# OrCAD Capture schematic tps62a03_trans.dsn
size D; title: TPS62A03x 3A, High-Efficiency, Synchronous, Buck Converter; rev: 1.0; note: Datasheet: SLUSFD4A     EVM: SLUUD12; note: Synchronous Step Down Converter
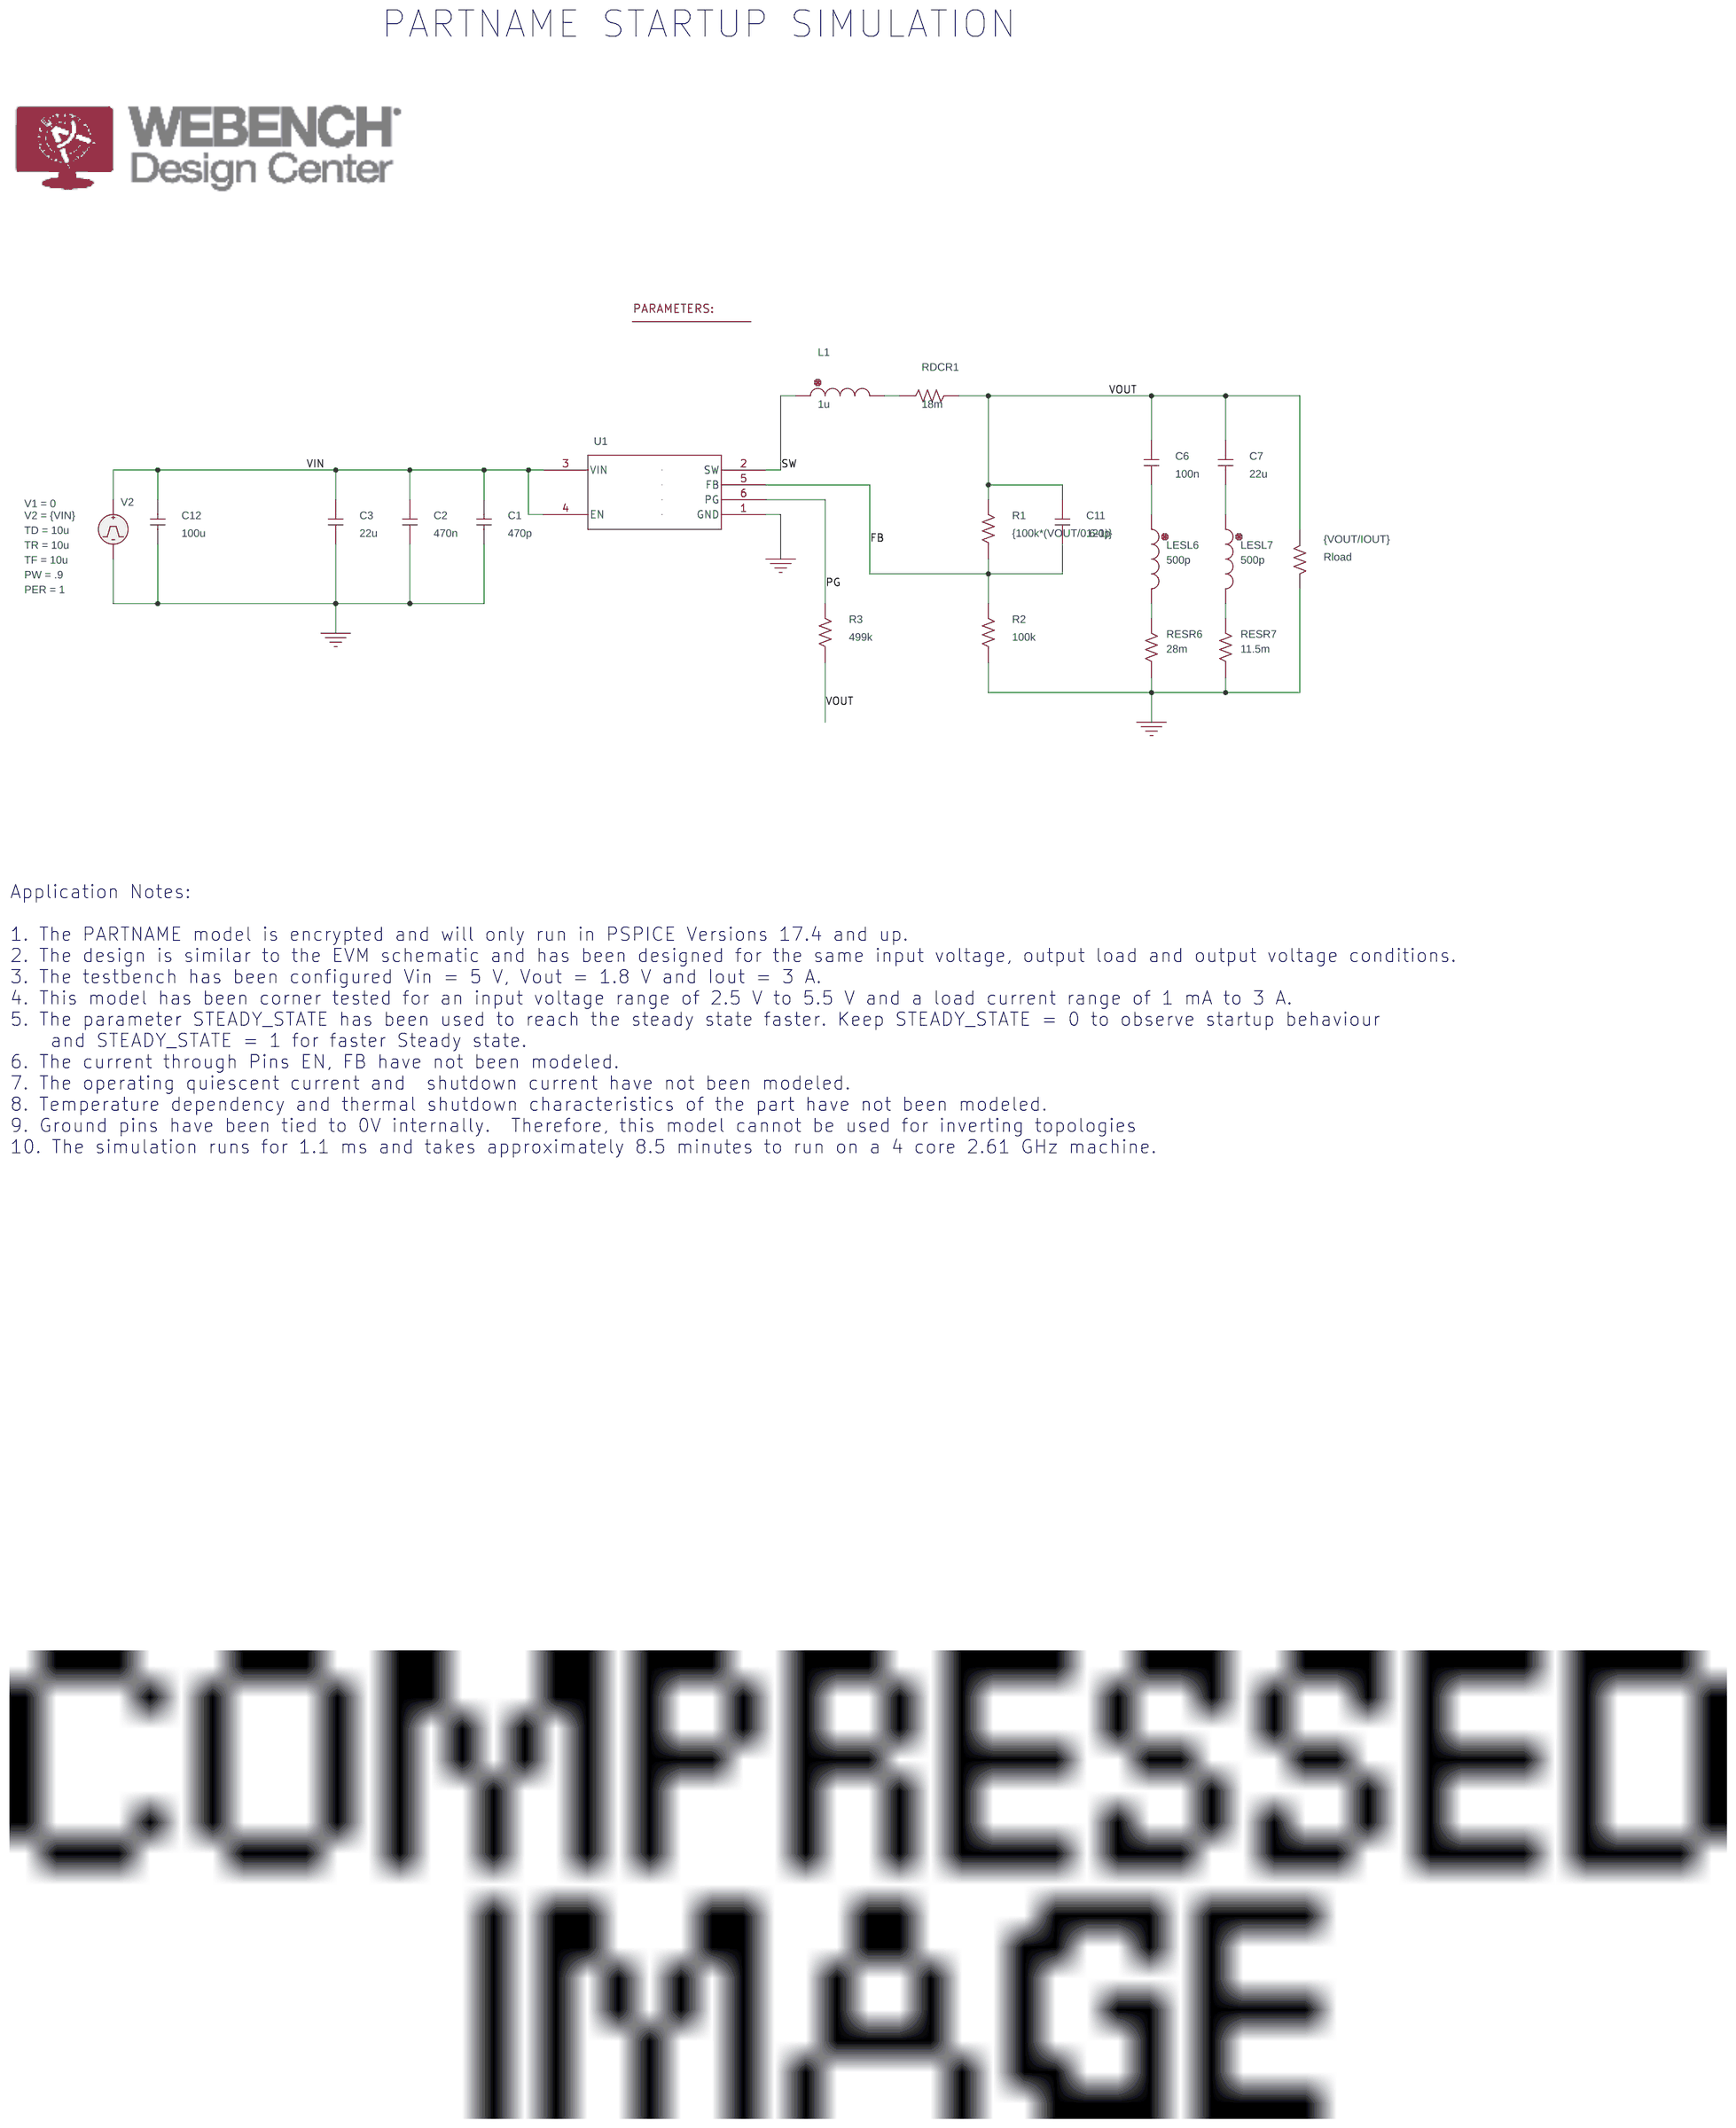
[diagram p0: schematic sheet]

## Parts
1  PARAM
C1  470p  [RAD/CK05]
C2  470n  [RAD/CK05]
C3  22u  [RAD/CK05]
C6  100n  [RAD/CK05]
C7  22u  [RAD/CK05]
C11  120p  [RAD/CK05]
C12  100u  [RAD/CK05]
L1  1u  [DISC/.350x.175/LS.200x.100/.034]
LESL6  500p  [DISC/.350x.175/LS.200x.100/.034]
LESL7  500p  [DISC/.350x.175/LS.200x.100/.034]
R1  {100k*(VOUT/0.6-1)}  [AX/RC05]
R2  100k  [AX/RC05]
R3  499k  [AX/RC05]
RDCR1  18m  [AX/RC05]
RESR6  28m  [AX/RC05]
RESR7  11.5m  [AX/RC05]
Rload  {VOUT/IOUT}  [AX/RC05]
U1  Value  [DRL0006A-MFG]
V2  VPULSE

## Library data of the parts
1 = PARAM: IOUT: 3; SS: 0; VIN: 5; VOUT: 1.8
C1-C3 C6 C7 C11 C12 = C
L1 LESL6 LESL7 = L
R1-R3 RDCR1 RESR6 RESR7 Rload = R
U1 = TPS62A03DRL_TRANS
V2 = VPULSE: PER: 1; PW: .9; TD: 10u; TF: 10u; TR: 10u; V1: 0; V2: {VIN}

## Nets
VIN: C1.2 C2.2 C3.2 C12.2 U1.3(VIN) U1.4(EN) V2.1(+)
0: C1.1 C2.1 C3.1 C12.1 R2.1 RESR6.1 RESR7.1 Rload.2 U1.1(GND) V2.2(-)
FB: C11.1 R1.1 R2.2 U1.5(FB)
PG: R3.2 U1.6(PG)
SW: L1.1 U1.2(SW)
VOUT: C6.2 C7.2 C11.2 R1.2 R3.1 RDCR1.2 Rload.1
N16775200: C6.1 LESL6.1
N16775206: C7.1 LESL7.1
N16775256: LESL6.2 RESR6.2
N16775262: LESL7.2 RESR7.2
N16775457: L1.2 RDCR1.1

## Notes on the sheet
- PARTNAME STARTUP SIMULATION
- Application Notes:
  1. The PARTNAME model is encrypted and will only run in PSPICE Versions 17.4 and up.
  2. The design is similar to the EVM schematic and has been designed for the same input voltage, output load and output voltage conditions.
  3. The testbench has been configured Vin = 5 V, Vout = 1.8 V and Iout = 3 A.
  4. This model has been corner tested for an input voltage range of 2.5 V to 5.5 V and a load current range of 1 mA to 3 A.
  5. The parameter STEADY_STATE has been used to reach the steady state faster. Keep STEADY_STATE = 0 to observe startup behaviour
      and STEADY_STATE = 1 for faster Steady state.
  6. The current through Pins EN, FB have not been modeled.
  7. The operating quiescent current and  shutdown current have not been modeled.
  8. Temperature dependency and thermal shutdown characteristics of the part have not been modeled.
  9. Ground pins have been tied to 0V internally.  Therefore, this model cannot be used for inverting topologies
  10. The simulation runs for 1.1 ms and takes approximately 8.5 minutes to run on a 4 core 2.61 GHz machine.
